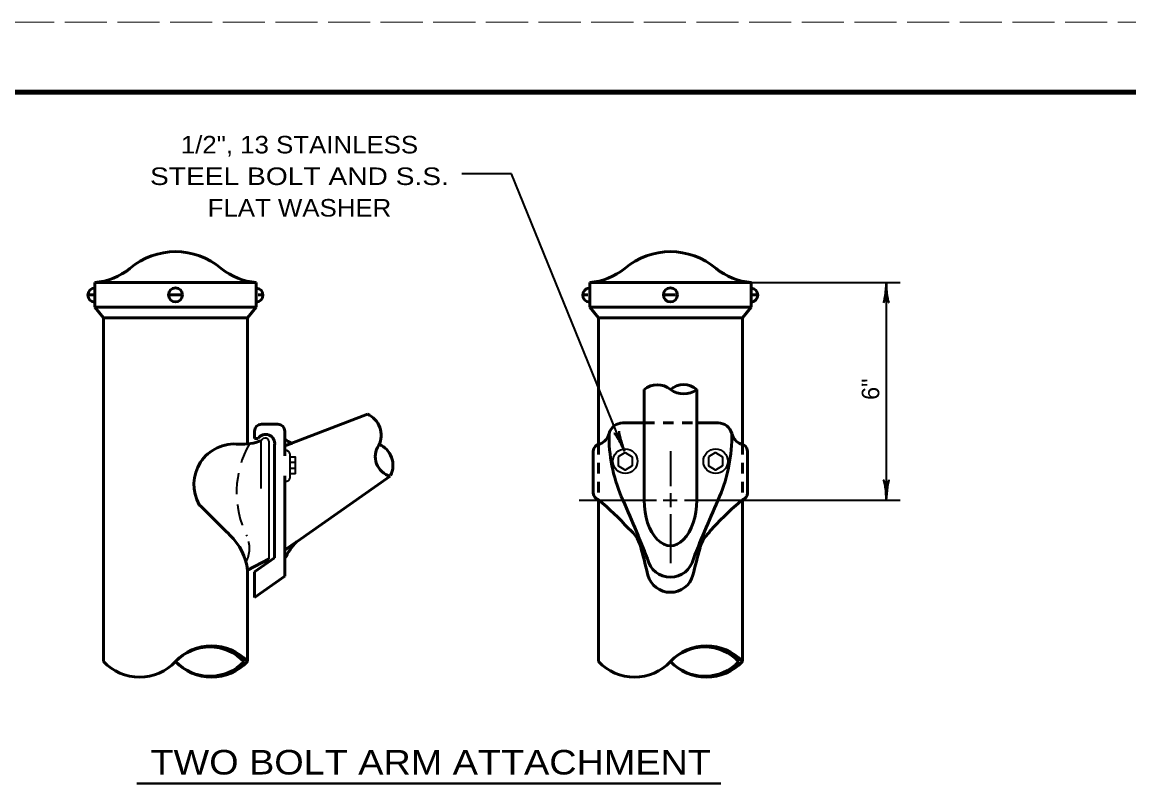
# Model space of a CAD drawing. Extents: x -1 to 679, y 1 to 441.
# Drawn here: x 360.8 to 518.5, y 331.6 to 440.9 of the extents above; entities that cross this region are included whole.
import ezdxf
from ezdxf.enums import TextEntityAlignment as Align

# ---------------------------------------------------------------- set-up
doc = ezdxf.new("R2010")
doc.units = 0
for name, pattern in [('LONG_DASHED', [7.5, 6, -1.5]), ('MEDIUM_DASHED', [4.5, 3, -1.5]), ('SHORT_DASHED', [2.7, 1.5, -1.2])]:
    doc.linetypes.add(name, pattern=pattern)
doc.layers.add('1', color=7, linetype='Continuous', lineweight=13)
doc.layers.add('61', color=7, linetype='Continuous', lineweight=35)

msp = doc.modelspace()

# ---------------------------------------------------------------- linework, layer by layer
at = {"layer": '1', "lineweight": 35}
for p, q in [((430.538, 419.224), (423.449, 419.224)), ((446.606, 379.747), (430.538, 419.224)), ((464.674, 403.739), (485.924, 403.739)), ((483.924, 403.739), (483.924, 372.739)), ((394.888, 374.382), (394.888, 381.202)), ((396.015, 364.382), (396.015, 380.882)), ((398.993, 375.931), (398.993, 379.28)), ((446.723, 379.516), (445.723, 378.891)), ((445.723, 378.891), (445.723, 377.641)), ((446.723, 379.516), (447.723, 378.891)), ((447.723, 378.891), (447.723, 377.641)), ((453.174, 379.739), (453.174, 374.724)), ((459.607, 379.512), (458.607, 378.887)), ((458.607, 378.887), (458.607, 377.637)), ((459.607, 379.512), (460.607, 378.887)), ((460.607, 378.887), (460.607, 377.637)), ((399.753, 378.104), (399.003, 378.104)), ((399.753, 377.255), (399.003, 377.255)), ((399.753, 376.505), (399.003, 376.505)), ((453.174, 373.724), (453.174, 371.725)), ((440.174, 372.739), (451.196, 372.739)), ((452.141, 372.739), (454.141, 372.739)), ((455.196, 372.739), (485.924, 372.739)), ((453.174, 370.724), (453.174, 363.739))]:
    msp.add_line(p, q, dxfattribs=at)
at = {"layer": '1', "lineweight": 53}
for p, q in [((371.174, 403.739), (394.174, 403.739)), ((371.174, 403.739), (371.174, 400.239)), ((394.174, 403.739), (394.174, 400.239)), ((441.674, 403.739), (464.674, 403.739)), ((441.674, 403.739), (441.674, 400.239)), ((464.674, 403.739), (464.674, 400.239)), ((370.18, 401.989), (370.924, 401.989)), ((381.917, 401.989), (383.417, 401.989)), ((394.424, 401.989), (395.127, 401.989)), ((440.68, 401.989), (441.424, 401.989)), ((452.417, 401.989), (453.917, 401.989)), ((464.924, 401.989), (465.627, 401.989)), ((371.174, 400.239), (394.174, 400.239)), ((371.174, 400.239), (372.424, 398.739)), ((394.174, 400.239), (392.924, 398.739)), ((441.674, 400.239), (464.674, 400.239)), ((441.674, 400.239), (442.924, 398.739)), ((464.674, 400.239), (463.424, 398.739)), ((372.424, 398.739), (372.424, 349.739)), ((372.424, 398.739), (392.924, 398.739)), ((392.924, 398.739), (392.924, 380.745)), ((442.924, 398.739), (463.424, 398.739)), ((442.924, 398.739), (442.924, 380.739)), ((463.424, 398.739), (463.424, 380.739)), ((449.424, 388.489), (449.424, 372.739)), ((456.924, 388.489), (456.924, 372.739)), ((398.241, 380.454), (410.01, 384.972)), ((394.924, 383.561), (397.241, 383.561)), ((446.38, 383.775), (449.424, 383.775)), ((456.924, 383.775), (459.968, 383.775)), ((393.924, 382.561), (393.924, 381.53)), ((398.241, 382.561), (398.241, 382.057)), ((398.241, 382.057), (398.241, 379.03)), ((393.924, 381.53), (394.424, 381.53)), ((396.791, 364.528), (396.791, 380.586)), ((442.174, 379.739), (442.174, 373.739)), ((464.174, 379.739), (464.174, 373.739)), ((398.241, 376.181), (398.241, 366.681)), ((398.241, 365.631), (413.257, 376.145)), ((442.924, 372.739), (442.924, 349.739)), ((463.424, 372.742), (463.424, 349.739)), ((398.241, 366.681), (398.241, 361.881)), ((392.924, 362.739), (396.015, 364.382)), ((393.924, 362.521), (396.791, 364.528)), ((392.924, 349.739), (392.924, 362.739)), ((393.924, 358.858), (393.924, 362.521)), ((393.924, 358.858), (398.241, 361.881))]:
    msp.add_line(p, q, dxfattribs=at)
at = {"layer": '1', "linetype": 'SHORT_DASHED', "lineweight": 53}
for p, q in [((449.424, 383.775), (456.924, 383.775)), ((442.924, 380.739), (442.924, 372.739)), ((463.424, 380.739), (463.424, 372.739))]:
    msp.add_line(p, q, dxfattribs=at)
at = {"layer": '1', "lineweight": 40}
msp.add_line((377.147, 332.351), (460.357, 332.351), dxfattribs=at)
at = {"layer": '1', "lineweight": 53}
for points in [[(399.331, 380.878), (398.245, 380.461), (398.245, 381.488)], [(398.253, 364.396), (398.253, 365.65), (399.909, 366.81)]]:
    msp.add_lwpolyline(points, dxfattribs=at)
at = {"layer": '1', "lineweight": 35}
for points in [[(399.753, 376.505), (399.753, 378.854), (399.003, 378.854)], [(447.723, 377.641), (446.723, 377.016), (445.723, 377.641)], [(460.607, 377.637), (459.607, 377.012), (458.607, 377.637)]]:
    msp.add_lwpolyline(points, dxfattribs=at)
at = {"layer": '1', "lineweight": 53}
for centre in [(382.667, 401.991), (453.167, 401.991)]:
    msp.add_circle(centre, 1, dxfattribs=at)
at = {"layer": '1', "lineweight": 35}
for centre in [(446.736, 378.294), (459.612, 378.286)]:
    msp.add_circle(centre, 1.75, dxfattribs=at)
at = {"layer": '1', "lineweight": 53}
for centre, radius, start, end in [((382.674, 398.212), 9.945, 49.18722, 130.81278), ((453.174, 398.212), 9.945, 49.18722, 130.81278), ((370.252, 413.295), 9.601, 275.5142, 308.08862), ((395.097, 413.295), 9.601, 231.91138, 264.4858), ((440.752, 413.295), 9.601, 275.5142, 308.08862), ((465.597, 413.295), 9.601, 231.91138, 264.4858), ((371.18, 401.963), 1, 90.3199, 269.6801), ((394.127, 401.963), 1, 272.67956, 87.32044), ((441.68, 401.963), 1, 90.3199, 269.6801), ((464.627, 401.963), 1, 272.67956, 87.32044), ((451.299, 386.318), 2.868, 49.17959, 130.82041), ((455.049, 386.424), 2.789, 47.76241, 132.23758), ((455.049, 391.212), 3.307, 235.45601, 304.54399), ((408.708, 381.988), 3.256, 333.96531, 66.42353), ((394.924, 382.561), 1, 90, 180), ((397.241, 382.561), 1, 0, 90), ((446.51, 381.596), 2.183, 93.41837, 162.8601), ((459.838, 381.596), 2.183, 17.1399, 86.58162), ((395.509, 380.81), 1.302, 350.09958, 146.42495), ((442.27, 382.763), 2.217, 294.0674, 346.32146), ((467.081, 381.974), 22.659, 179.33091, 202.67617), ((439.267, 381.974), 22.659, 337.32383, 0.66909), ((464.078, 382.763), 2.217, 193.67854, 245.9326), ((391.036, 374.981), 5.759, 83.22236, 210.1126), ((392, 389.18), 8.485, 268.07998, 289.90391), ((399.642, 382.703), 1.851, 221.01419, 260.32206), ((414.017, 378.93), 2.886, 145.65086, 254.73799), ((410.39, 377.701), 3.256, 333.96531, 66.42353), ((443.231, 379.682), 1.058, 93.07015, 176.92984), ((463.118, 379.682), 1.058, 3.07016, 86.92985), ((443.231, 373.796), 1.058, 183.07016, 253.15341), ((463.118, 373.796), 1.058, 286.84659, 356.92984), ((415.986, 340.293), 42.205, 42.29957, 50.33685), ((265.123, 291.981), 198.45, 21.39177, 24.17121), ((645.416, 290.221), 202.994, 155.85991, 158.57712), ((490.363, 340.293), 42.205, 129.66315, 138.49633), ((1492.449, 1478.628), 1564.779, 225.00367, 225.22952), ((384.909, 361.856), 8.063, 6.28285, 46.84726), ((444.108, 364.755), 5.012, 9.48157, 51.86654), ((462.441, 364.425), 5.287, 133.87214, 169.50589), ((406.766, 360.33), 9.434, 136.62273, 154.46868), ((534.738, 343.744), 80.46, 163.98892, 166.86491), ((371.611, 343.744), 80.46, 13.13509, 15.74771), ((453.174, 365.119), 3.359, 193.00171, 346.99829), ((453.174, 362.931), 3.333, 195.72161, 344.27839), ((387.799, 344.961), 7.006, 42.99091, 137.00909), ((387.541, 345.086), 6.732, 43.44505, 136.28697), ((458.299, 344.961), 7.006, 42.99091, 137.00909), ((458.041, 345.086), 6.732, 43.44505, 136.28697), ((377.549, 354.516), 7.006, 222.99091, 317.00909), ((387.562, 354.358), 6.725, 223.38031, 316.35171), ((387.799, 354.516), 7.006, 222.99091, 317.00909), ((448.049, 354.516), 7.006, 222.99091, 317.00909), ((458.062, 354.358), 6.725, 223.38031, 316.35171), ((458.299, 354.516), 7.006, 222.99091, 317.00909)]:
    msp.add_arc(centre, radius, start, end, dxfattribs=at)
at = {"layer": '1', "lineweight": 35}
for centre, radius, start, end in [((395.437, 380.99), 0.588, 349.37883, 158.91973), ((398.282, 379.107), 0.732, 13.64106, 87.59419), ((398.282, 376.104), 0.732, 272.40581, 346.35894)]:
    msp.add_arc(centre, radius, start, end, dxfattribs=at)
at = {"layer": '1', "linetype": 'MEDIUM_DASHED', "lineweight": 35}
for centre, radius, start, end in [((405.484, 373.824), 14.115, 150.47291, 206.06704), ((389.217, 365.868), 3.994, 330.81735, 26.04877)]:
    msp.add_arc(centre, radius, start, end, dxfattribs=at)
at = {"layer": '1', "lineweight": 40}
for centre, major_axis, ratio, start_param, end_param in [((483.713, 402.618), (0.176, 1.756), 0.07063, 3.1407148, 5.41811), ((484.201, 402.648), (-0.156, 1.786), 0.122415, 0.8963533, 3.1415927), ((445.938, 380.653), (0.818, -1.595), 0.122415, 0.8963533, 3.1415927), ((446.379, 380.864), (-0.499, 1.693), 0.07063, 6.2823074, 8.5597026), ((483.648, 373.83), (0.156, -1.786), 0.122415, 0.8963533, 3.1415927), ((484.136, 373.859), (-0.176, -1.756), 0.07063, 3.1407148, 5.41811)]:
    msp.add_ellipse(centre, major_axis=major_axis, ratio=ratio, start_param=start_param, end_param=end_param, dxfattribs=at)
at = {"layer": '1', "lineweight": 53}
msp.add_ellipse((453.174, 372.739), major_axis=(0, 6.5), ratio=0.576878, start_param=1.5707963, end_param=4.712389, dxfattribs=at)
at = {"layer": '61', "linetype": 'LONG_DASHED', "lineweight": 13}
msp.add_line((-0.608, 440.866), (679.412, 440.866), dxfattribs=at)
at = {"layer": '61', "lineweight": 158}
msp.add_lwpolyline([(668.432, 430.866), (29.392, 430.866), (29.392, 10.846)], dxfattribs=at)

# ---------------------------------------------------------------- texts
at = {"layer": '1'}
for s, height, width, p in [('1/2", 13 STAINLESS', 2.5, 1.1, (400.324, 422.151)), ('STEEL BOLT AND S.S.', 2.5, 1.2, (400.324, 417.651)), ('FLAT WASHER', 2.5, 1.1, (400.324, 413.151)), ('TWO BOLT ARM ATTACHMENT', 3.5, 1.15, (419.018, 333.634))]:
    msp.add_text(s, height=height, dxfattribs=dict(at, width=width)).set_placement(p, align=Align.CENTER)
msp.add_text('6"', height=2.5, rotation=90, dxfattribs=at).set_placement((482.927, 387.021))

doc.saveas('drawing.dxf')
